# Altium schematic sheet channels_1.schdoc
size 400 x 299 mm; Device: default420x319; Symbol: default420x319; Name: default420x319; Size: "User"; Id: /; File: channels_1; Sheet: /
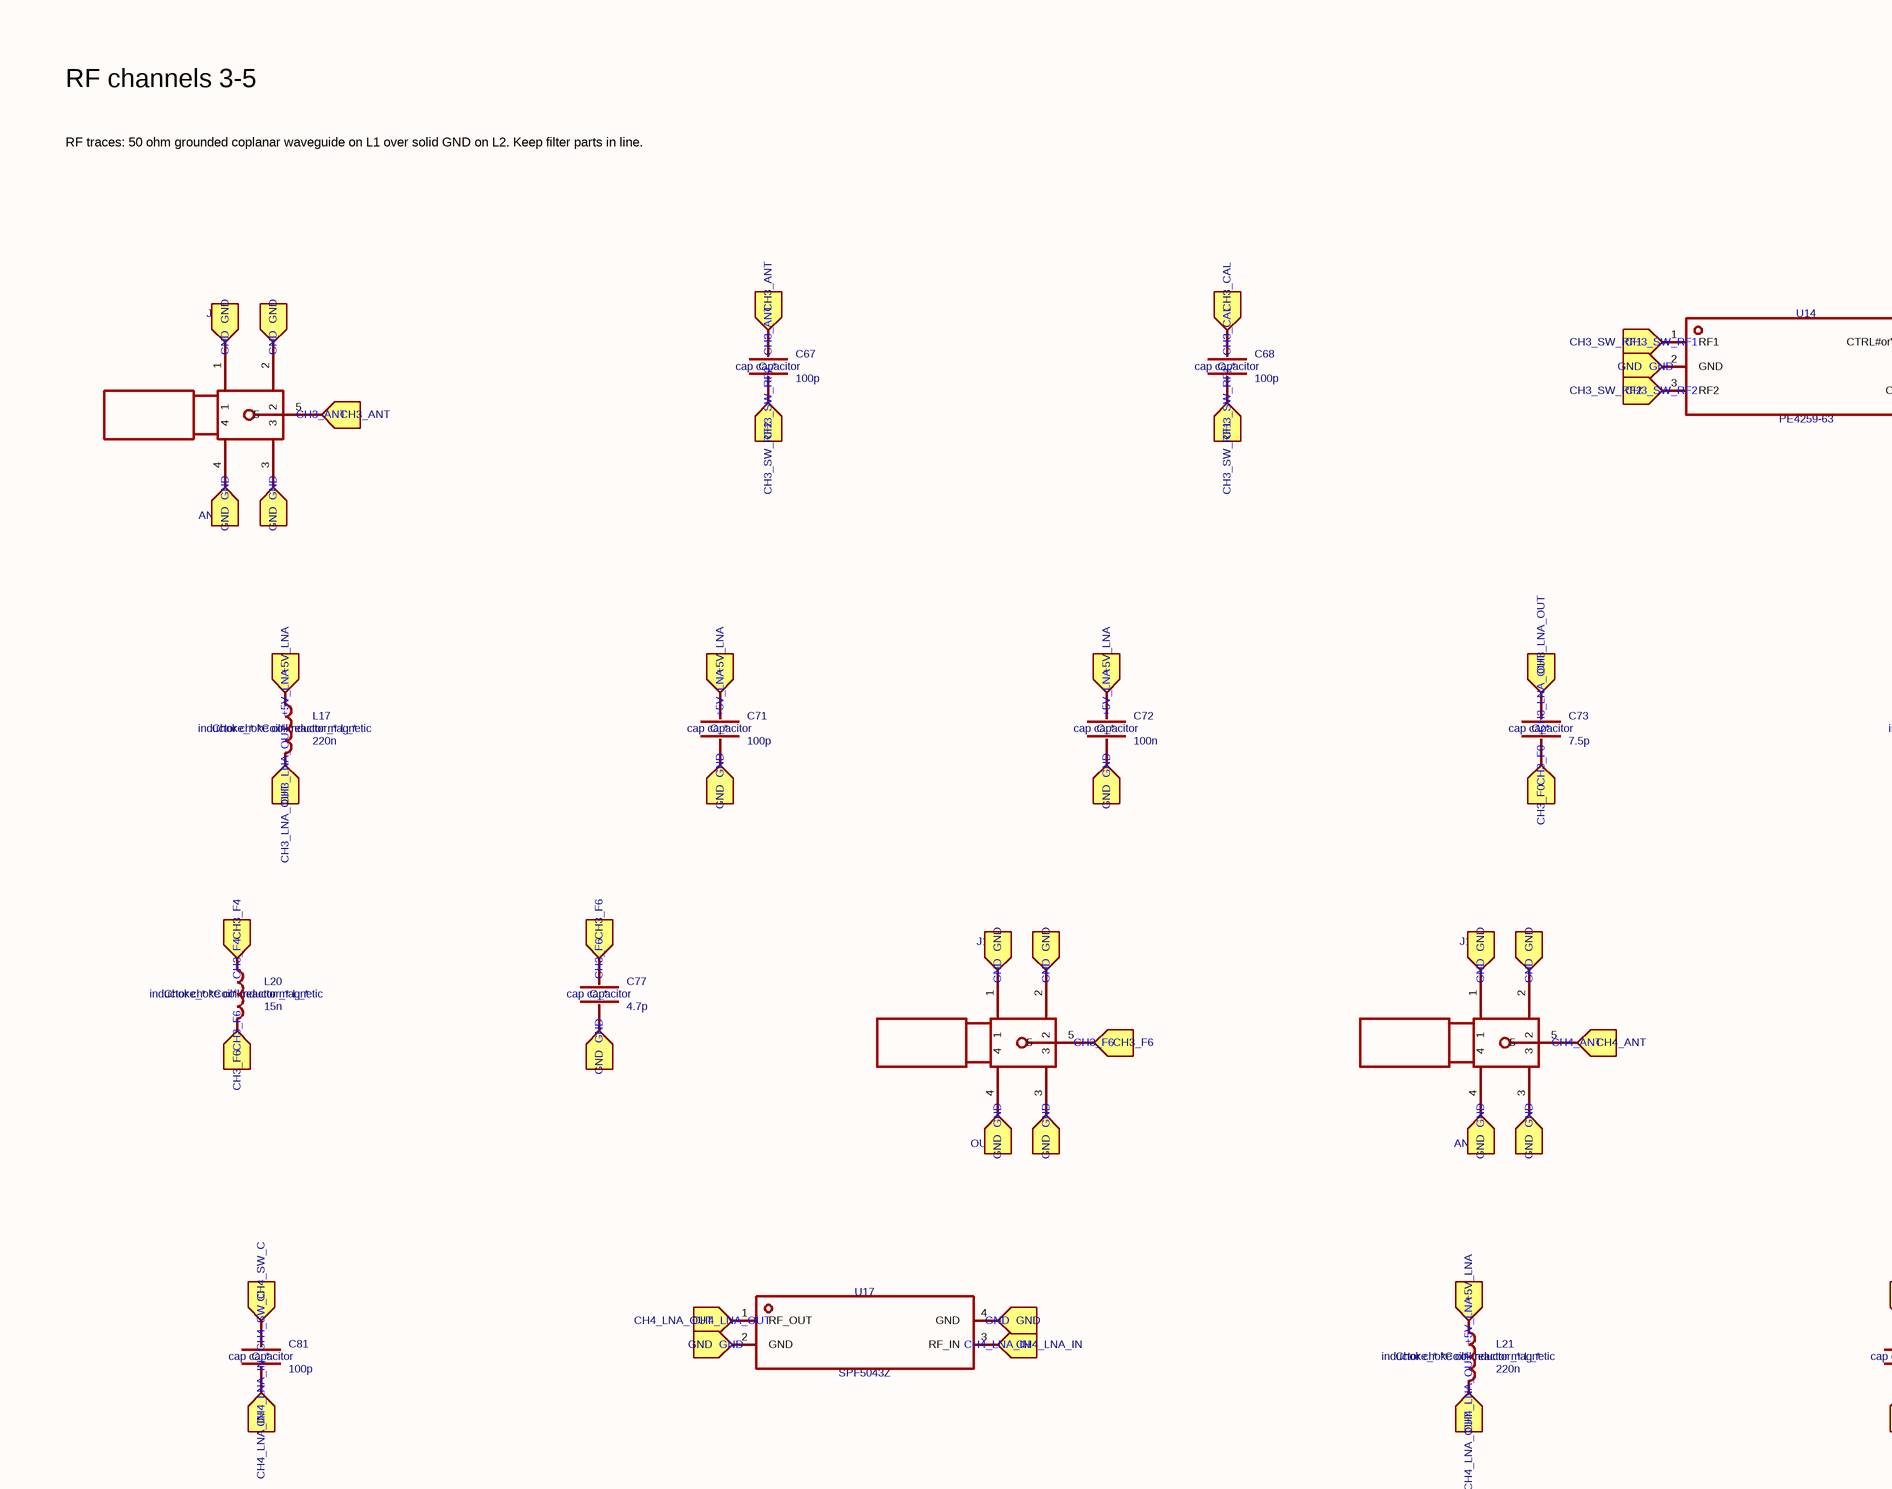
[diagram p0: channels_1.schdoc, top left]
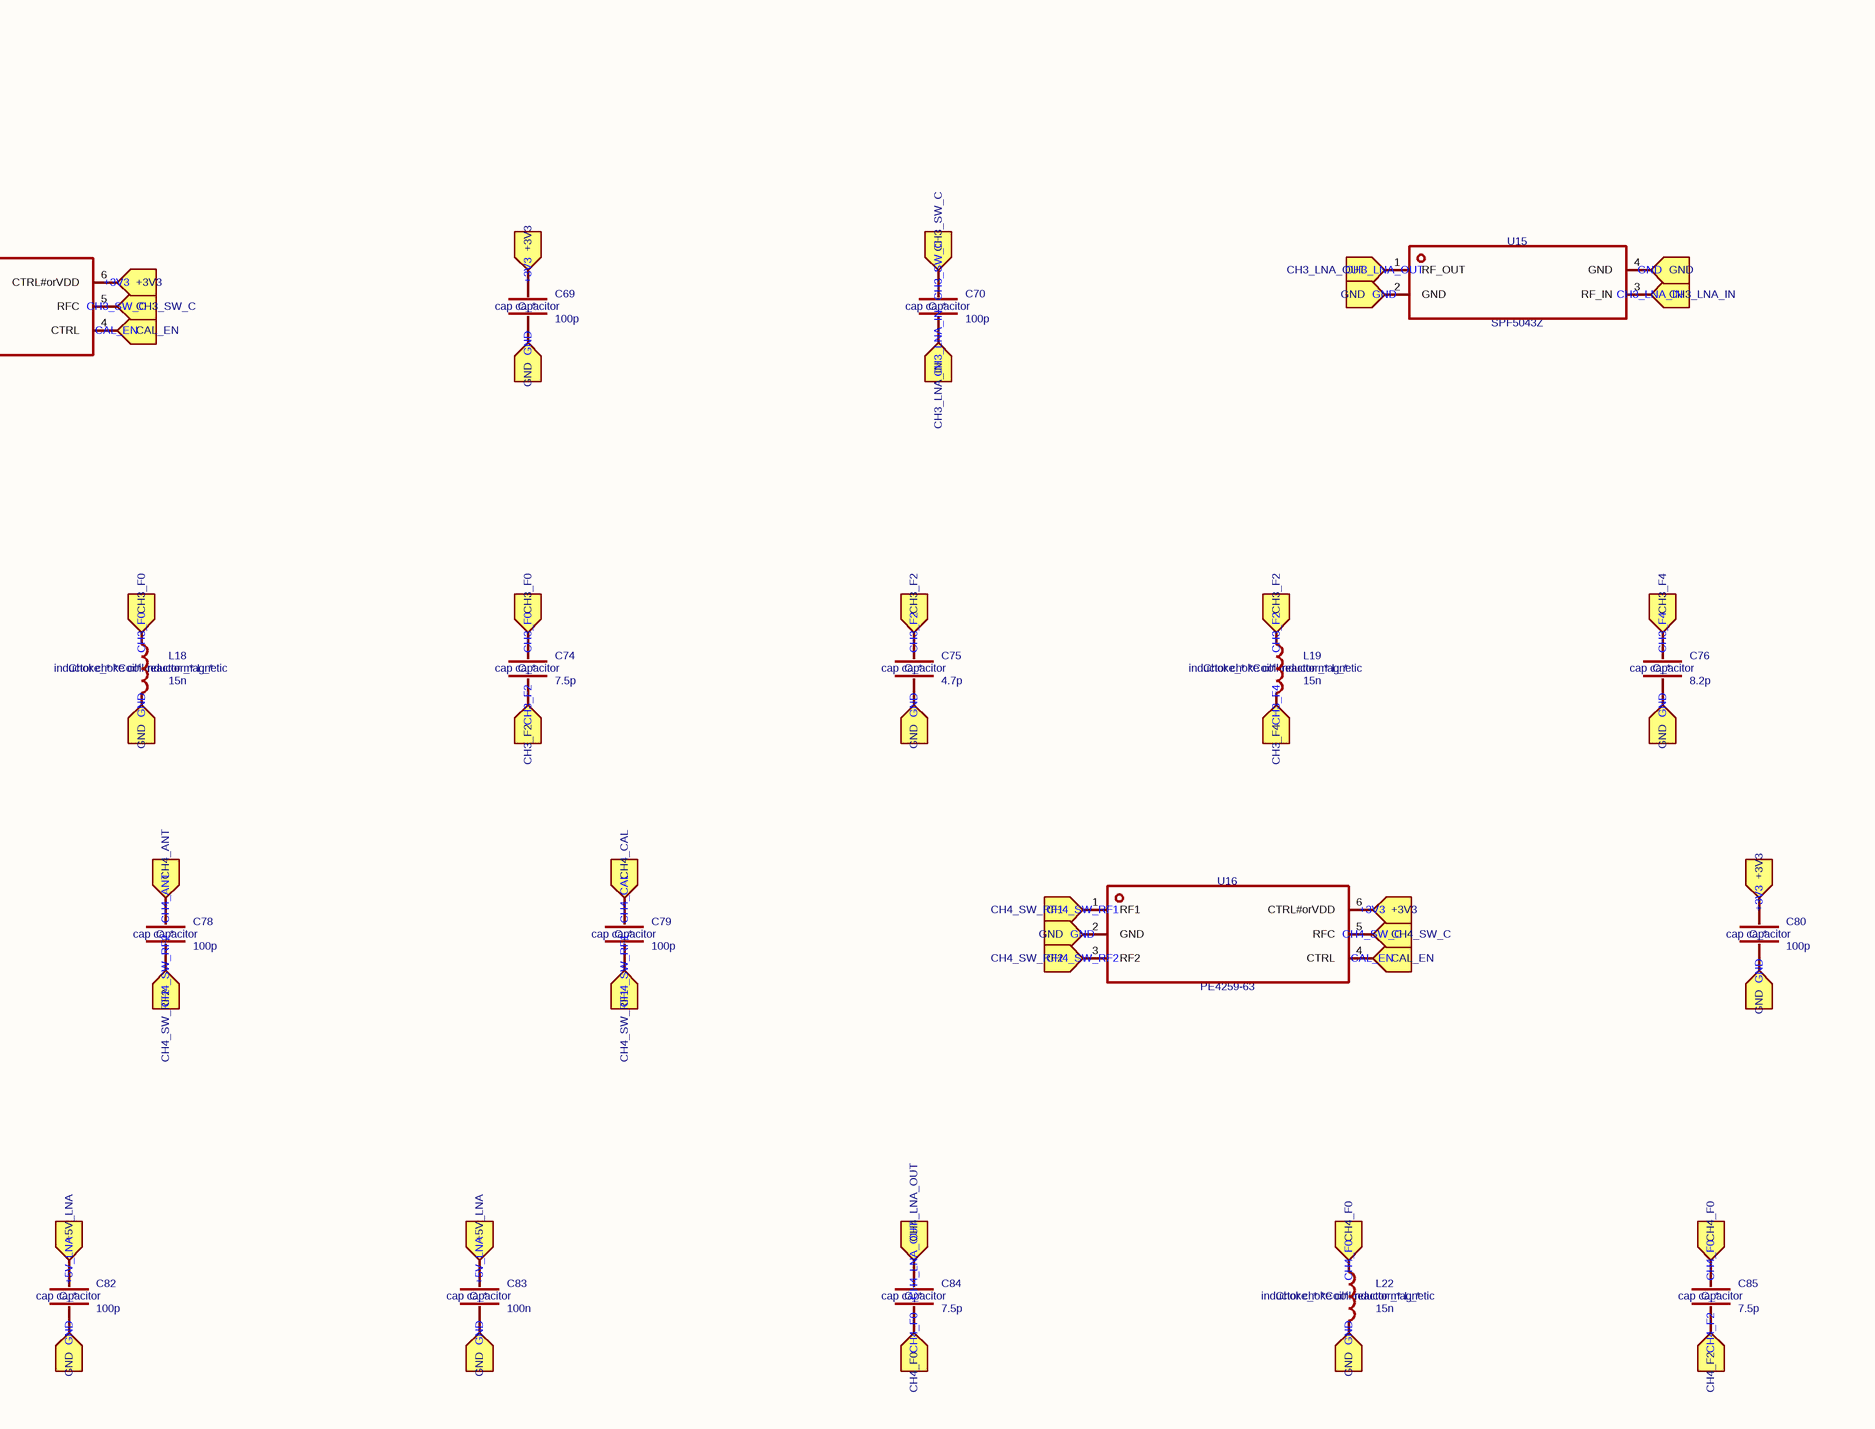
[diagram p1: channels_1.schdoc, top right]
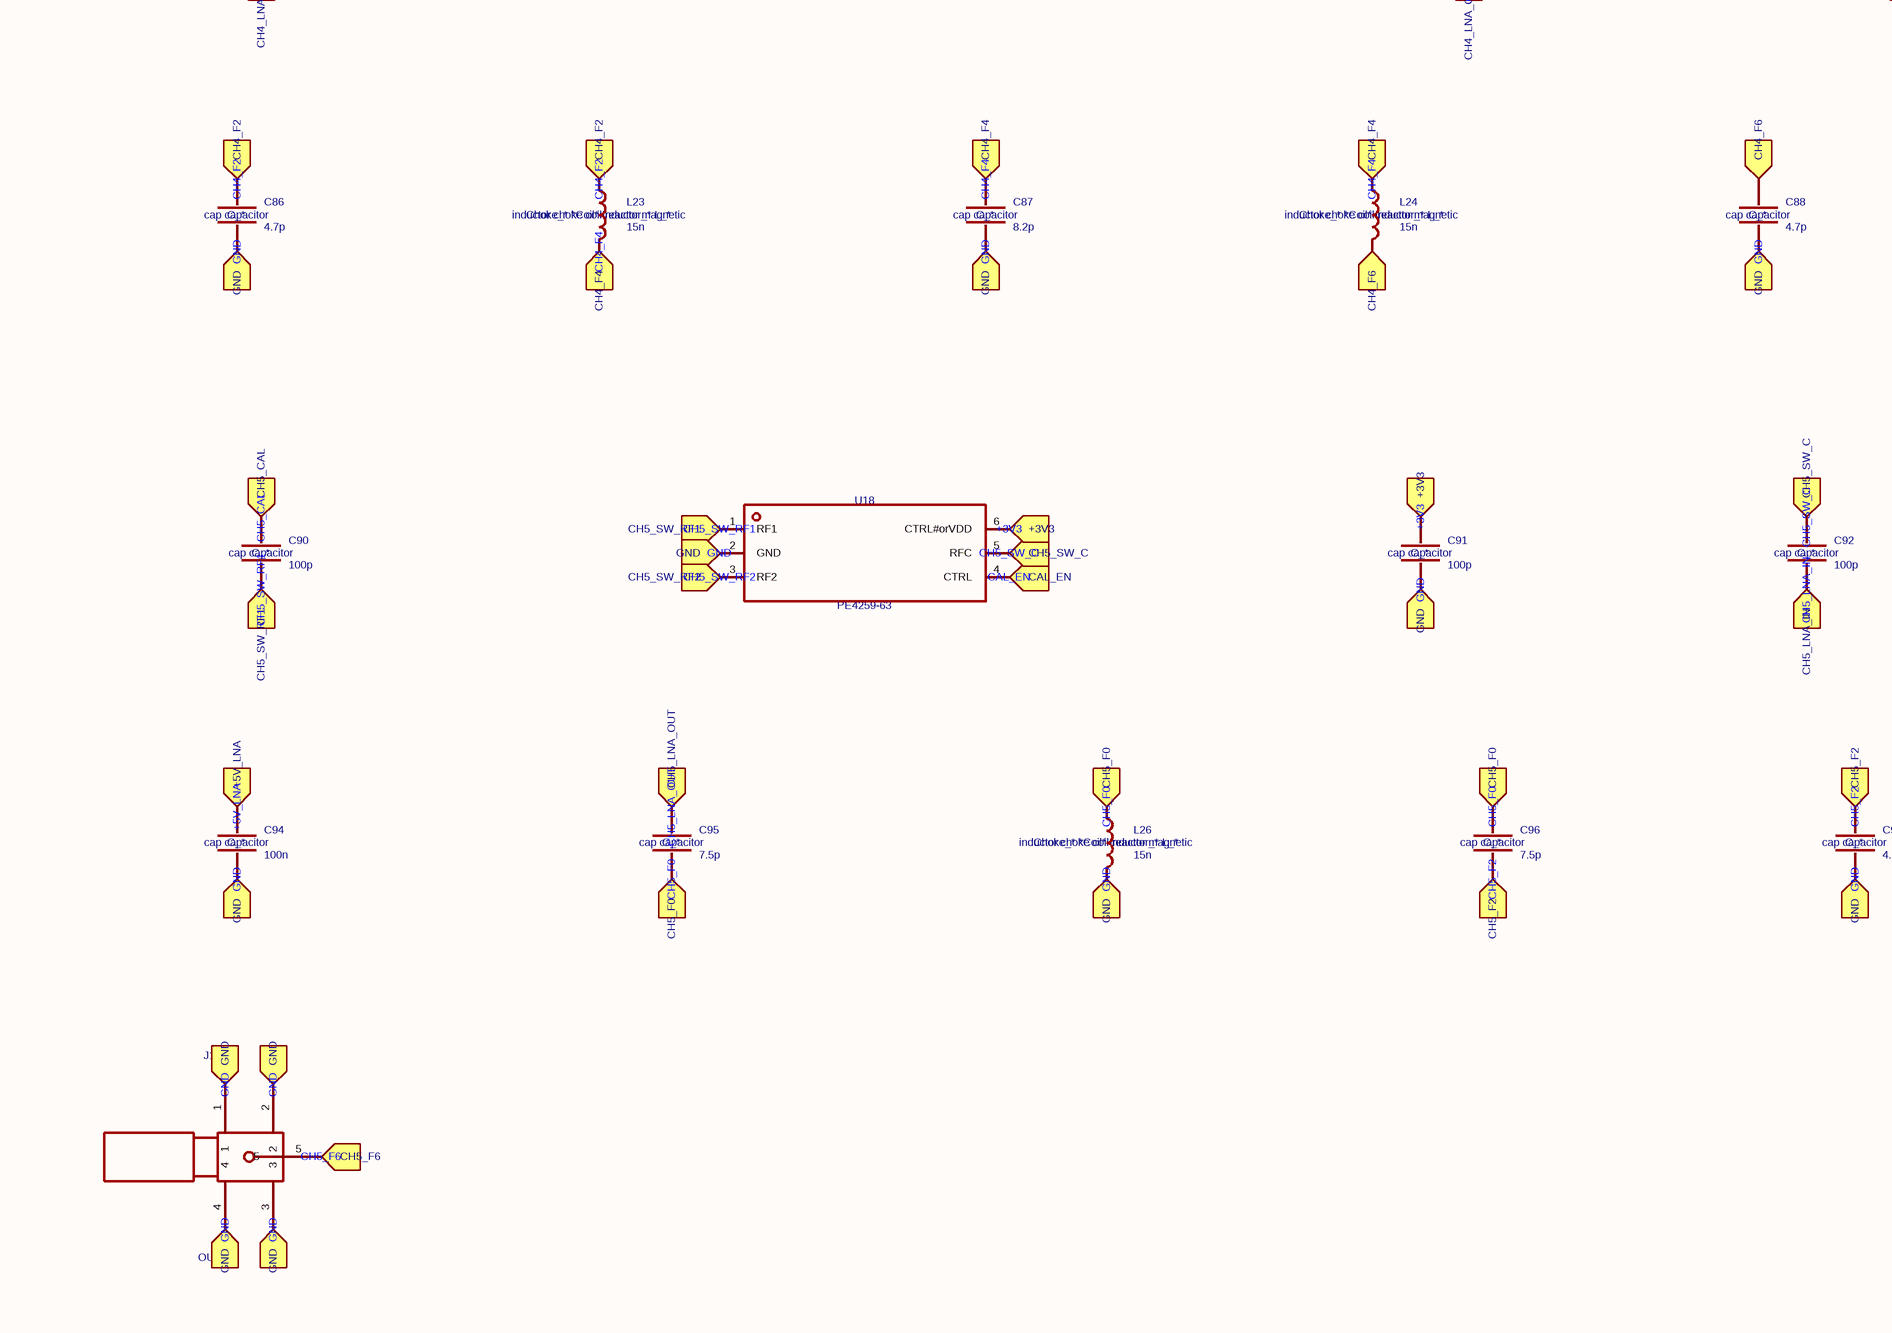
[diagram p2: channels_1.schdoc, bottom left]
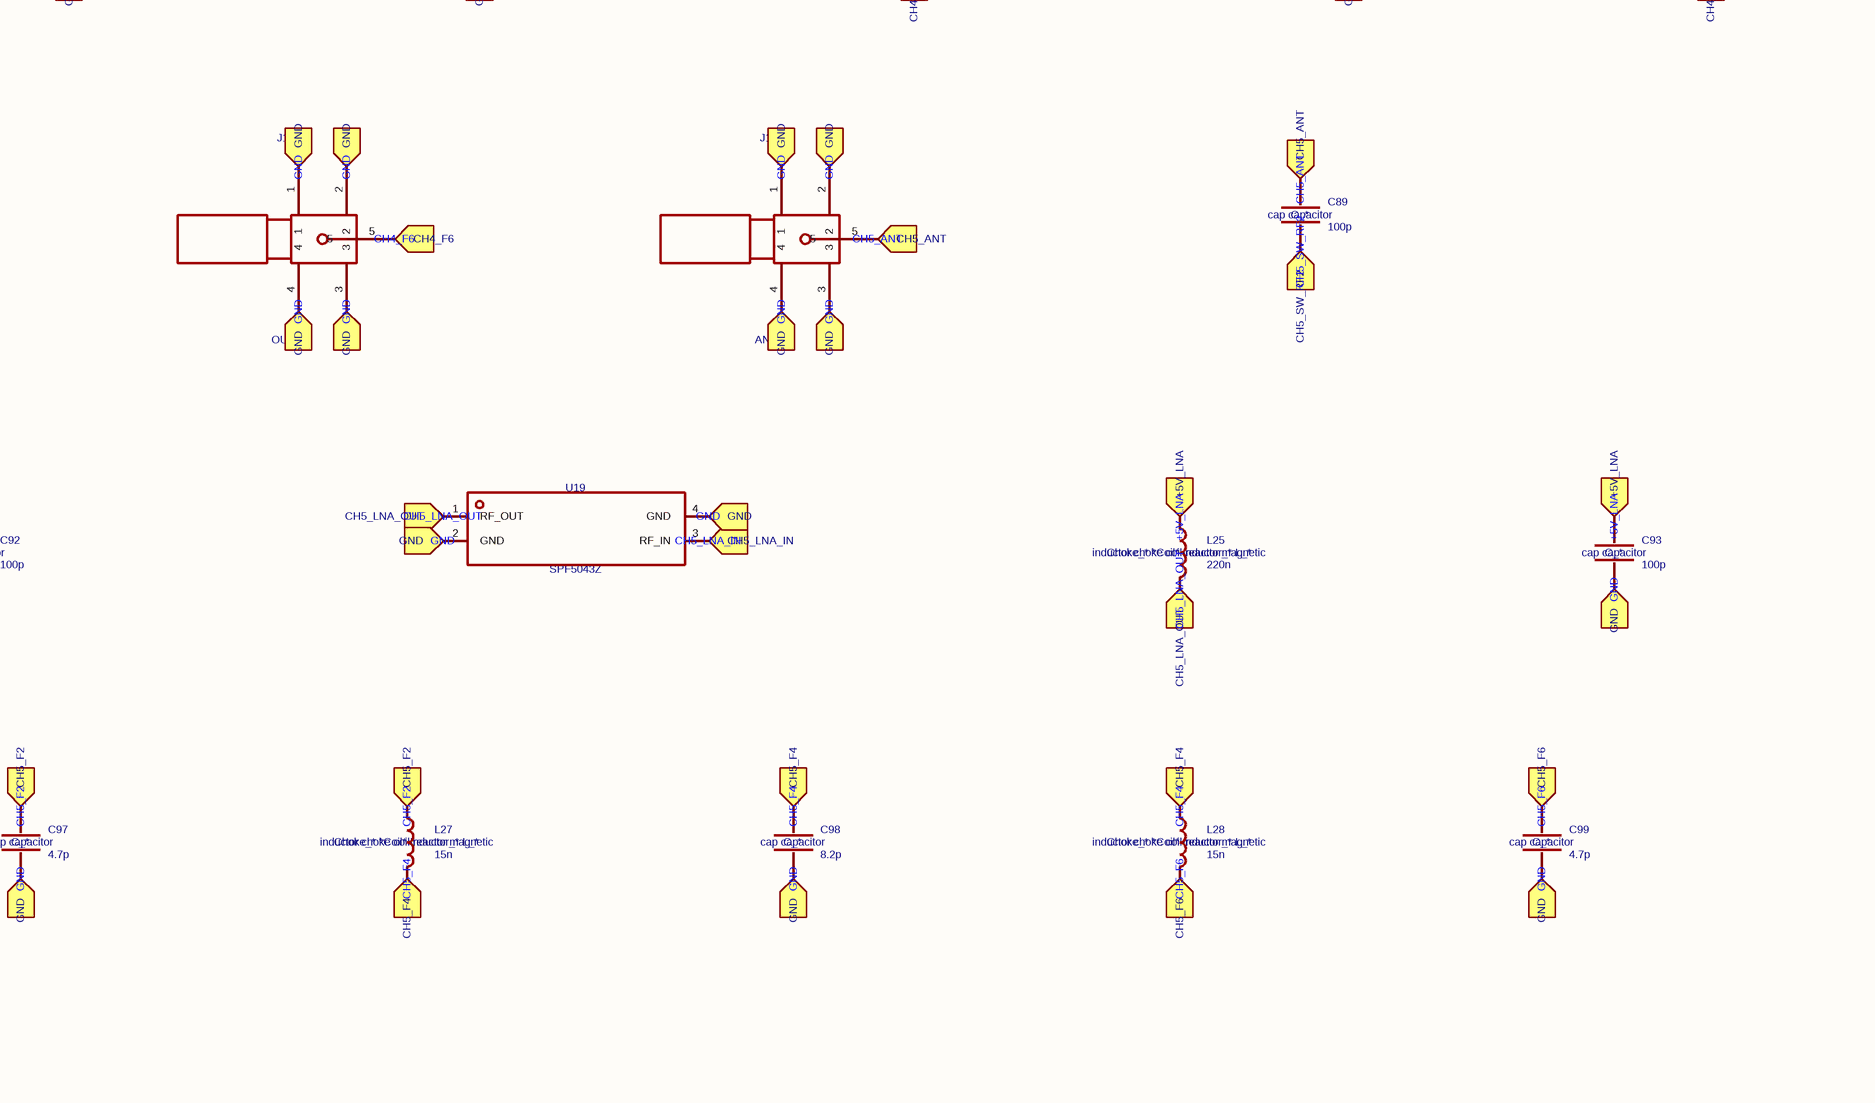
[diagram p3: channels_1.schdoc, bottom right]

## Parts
C67  value 100p  ki_keywords: cap capacitor  ki_fp_filters: C_*  [Capacitor_SMD:C_0402_1005Metric]  (hidden comment: Device_C)
C68  value 100p  ki_keywords: cap capacitor  ki_fp_filters: C_*  [Capacitor_SMD:C_0402_1005Metric]  (hidden comment: Device_C)
C69  value 100p  ki_keywords: cap capacitor  ki_fp_filters: C_*  [Capacitor_SMD:C_0402_1005Metric]  (hidden comment: Device_C)
C70  value 100p  ki_keywords: cap capacitor  ki_fp_filters: C_*  [Capacitor_SMD:C_0402_1005Metric]  (hidden comment: Device_C)
C71  value 100p  ki_keywords: cap capacitor  ki_fp_filters: C_*  [Capacitor_SMD:C_0402_1005Metric]  (hidden comment: Device_C)
C72  value 100n  ki_keywords: cap capacitor  ki_fp_filters: C_*  [Capacitor_SMD:C_0402_1005Metric]  (hidden comment: Device_C)
C73  value 7.5p  ki_keywords: cap capacitor  ki_fp_filters: C_*  [Capacitor_SMD:C_0402_1005Metric]  (hidden comment: Device_C)
C74  value 7.5p  ki_keywords: cap capacitor  ki_fp_filters: C_*  [Capacitor_SMD:C_0402_1005Metric]  (hidden comment: Device_C)
C75  value 4.7p  ki_keywords: cap capacitor  ki_fp_filters: C_*  [Capacitor_SMD:C_0402_1005Metric]  (hidden comment: Device_C)
C76  value 8.2p  ki_keywords: cap capacitor  ki_fp_filters: C_*  [Capacitor_SMD:C_0402_1005Metric]  (hidden comment: Device_C)
C77  value 4.7p  ki_keywords: cap capacitor  ki_fp_filters: C_*  [Capacitor_SMD:C_0402_1005Metric]  (hidden comment: Device_C)
C78  value 100p  ki_keywords: cap capacitor  ki_fp_filters: C_*  [Capacitor_SMD:C_0402_1005Metric]  (hidden comment: Device_C)
C79  value 100p  ki_keywords: cap capacitor  ki_fp_filters: C_*  [Capacitor_SMD:C_0402_1005Metric]  (hidden comment: Device_C)
C80  value 100p  ki_keywords: cap capacitor  ki_fp_filters: C_*  [Capacitor_SMD:C_0402_1005Metric]  (hidden comment: Device_C)
C81  value 100p  ki_keywords: cap capacitor  ki_fp_filters: C_*  [Capacitor_SMD:C_0402_1005Metric]  (hidden comment: Device_C)
C82  value 100p  ki_keywords: cap capacitor  ki_fp_filters: C_*  [Capacitor_SMD:C_0402_1005Metric]  (hidden comment: Device_C)
C83  value 100n  ki_keywords: cap capacitor  ki_fp_filters: C_*  [Capacitor_SMD:C_0402_1005Metric]  (hidden comment: Device_C)
C84  value 7.5p  ki_keywords: cap capacitor  ki_fp_filters: C_*  [Capacitor_SMD:C_0402_1005Metric]  (hidden comment: Device_C)
C85  value 7.5p  ki_keywords: cap capacitor  ki_fp_filters: C_*  [Capacitor_SMD:C_0402_1005Metric]  (hidden comment: Device_C)
C86  value 4.7p  ki_keywords: cap capacitor  ki_fp_filters: C_*  [Capacitor_SMD:C_0402_1005Metric]  (hidden comment: Device_C)
C87  value 8.2p  ki_keywords: cap capacitor  ki_fp_filters: C_*  [Capacitor_SMD:C_0402_1005Metric]  (hidden comment: Device_C)
C88  value 4.7p  ki_keywords: cap capacitor  ki_fp_filters: C_*  [Capacitor_SMD:C_0402_1005Metric]  (hidden comment: Device_C)
C89  value 100p  ki_keywords: cap capacitor  ki_fp_filters: C_*  [Capacitor_SMD:C_0402_1005Metric]  (hidden comment: Device_C)
C90  value 100p  ki_keywords: cap capacitor  ki_fp_filters: C_*  [Capacitor_SMD:C_0402_1005Metric]  (hidden comment: Device_C)
C91  value 100p  ki_keywords: cap capacitor  ki_fp_filters: C_*  [Capacitor_SMD:C_0402_1005Metric]  (hidden comment: Device_C)
C92  value 100p  ki_keywords: cap capacitor  ki_fp_filters: C_*  [Capacitor_SMD:C_0402_1005Metric]  (hidden comment: Device_C)
C93  value 100p  ki_keywords: cap capacitor  ki_fp_filters: C_*  [Capacitor_SMD:C_0402_1005Metric]  (hidden comment: Device_C)
C94  value 100n  ki_keywords: cap capacitor  ki_fp_filters: C_*  [Capacitor_SMD:C_0402_1005Metric]  (hidden comment: Device_C)
C95  value 7.5p  ki_keywords: cap capacitor  ki_fp_filters: C_*  [Capacitor_SMD:C_0402_1005Metric]  (hidden comment: Device_C)
C96  value 7.5p  ki_keywords: cap capacitor  ki_fp_filters: C_*  [Capacitor_SMD:C_0402_1005Metric]  (hidden comment: Device_C)
C97  value 4.7p  ki_keywords: cap capacitor  ki_fp_filters: C_*  [Capacitor_SMD:C_0402_1005Metric]  (hidden comment: Device_C)
C98  value 8.2p  ki_keywords: cap capacitor  ki_fp_filters: C_*  [Capacitor_SMD:C_0402_1005Metric]  (hidden comment: Device_C)
C99  value 4.7p  ki_keywords: cap capacitor  ki_fp_filters: C_*  [Capacitor_SMD:C_0402_1005Metric]  (hidden comment: Device_C)
J9  value ANT3  [prc:SMA-TH_BWSMA-KE-Z001]  (hidden comment: prc_BWSMA-KE-Z001)
J10  value OUT3  [prc:SMA-TH_BWSMA-KE-Z001]  (hidden comment: prc_BWSMA-KE-Z001)
J11  value ANT4  [prc:SMA-TH_BWSMA-KE-Z001]  (hidden comment: prc_BWSMA-KE-Z001)
J12  value OUT4  [prc:SMA-TH_BWSMA-KE-Z001]  (hidden comment: prc_BWSMA-KE-Z001)
J13  value ANT5  [prc:SMA-TH_BWSMA-KE-Z001]  (hidden comment: prc_BWSMA-KE-Z001)
J14  value OUT5  [prc:SMA-TH_BWSMA-KE-Z001]  (hidden comment: prc_BWSMA-KE-Z001)
L17  value 220n  ki_keywords: inductor choke coil reactor magnetic  ki_fp_filters: Choke_* *Coil* Inductor_* L_*  [Inductor_SMD:L_0603_1608Metric]  (hidden comment: Device_L)
L18  value 15n  ki_keywords: inductor choke coil reactor magnetic  ki_fp_filters: Choke_* *Coil* Inductor_* L_*  [Inductor_SMD:L_0402_1005Metric]  (hidden comment: Device_L)
L19  value 15n  ki_keywords: inductor choke coil reactor magnetic  ki_fp_filters: Choke_* *Coil* Inductor_* L_*  [Inductor_SMD:L_0402_1005Metric]  (hidden comment: Device_L)
L20  value 15n  ki_keywords: inductor choke coil reactor magnetic  ki_fp_filters: Choke_* *Coil* Inductor_* L_*  [Inductor_SMD:L_0402_1005Metric]  (hidden comment: Device_L)
L21  value 220n  ki_keywords: inductor choke coil reactor magnetic  ki_fp_filters: Choke_* *Coil* Inductor_* L_*  [Inductor_SMD:L_0603_1608Metric]  (hidden comment: Device_L)
L22  value 15n  ki_keywords: inductor choke coil reactor magnetic  ki_fp_filters: Choke_* *Coil* Inductor_* L_*  [Inductor_SMD:L_0402_1005Metric]  (hidden comment: Device_L)
L23  value 15n  ki_keywords: inductor choke coil reactor magnetic  ki_fp_filters: Choke_* *Coil* Inductor_* L_*  [Inductor_SMD:L_0402_1005Metric]  (hidden comment: Device_L)
L24  value 15n  ki_keywords: inductor choke coil reactor magnetic  ki_fp_filters: Choke_* *Coil* Inductor_* L_*  [Inductor_SMD:L_0402_1005Metric]  (hidden comment: Device_L)
L25  value 220n  ki_keywords: inductor choke coil reactor magnetic  ki_fp_filters: Choke_* *Coil* Inductor_* L_*  [Inductor_SMD:L_0603_1608Metric]  (hidden comment: Device_L)
L26  value 15n  ki_keywords: inductor choke coil reactor magnetic  ki_fp_filters: Choke_* *Coil* Inductor_* L_*  [Inductor_SMD:L_0402_1005Metric]  (hidden comment: Device_L)
L27  value 15n  ki_keywords: inductor choke coil reactor magnetic  ki_fp_filters: Choke_* *Coil* Inductor_* L_*  [Inductor_SMD:L_0402_1005Metric]  (hidden comment: Device_L)
L28  value 15n  ki_keywords: inductor choke coil reactor magnetic  ki_fp_filters: Choke_* *Coil* Inductor_* L_*  [Inductor_SMD:L_0402_1005Metric]  (hidden comment: Device_L)
U14  value PE4259-63  [prc:SC-70-6_L2.2-W1.3-P0.65-LS2.1-BL]  (hidden comment: prc_PE4259-63)
U15  value SPF5043Z  [prc:SOT343_L2.0-W1.3-P1.30-LS2.1-BL]  (hidden comment: prc_SPF5043Z)
U16  value PE4259-63  [prc:SC-70-6_L2.2-W1.3-P0.65-LS2.1-BL]  (hidden comment: prc_PE4259-63)
U17  value SPF5043Z  [prc:SOT343_L2.0-W1.3-P1.30-LS2.1-BL]  (hidden comment: prc_SPF5043Z)
U18  value PE4259-63  [prc:SC-70-6_L2.2-W1.3-P0.65-LS2.1-BL]  (hidden comment: prc_PE4259-63)
U19  value SPF5043Z  [prc:SOT343_L2.0-W1.3-P1.30-LS2.1-BL]  (hidden comment: prc_SPF5043Z)

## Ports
+3V3 (in), +5V_LNA (in), CAL_EN (in), CH3_ANT (in), CH3_CAL (in), CH3_F0 (in), CH3_F2 (in), CH3_F4 (in), CH3_F6 (in), CH3_LNA_IN (in), CH3_LNA_OUT (in), CH3_SW_C (in), CH3_SW_RF1 (in), CH3_SW_RF2 (in), CH4_ANT (in), CH4_CAL (in), CH4_F0 (in), CH4_F2 (in), CH4_F4 (in), CH4_F6 (in), CH4_LNA_IN (in), CH4_LNA_OUT (in), CH4_SW_C (in), CH4_SW_RF1 (in), CH4_SW_RF2 (in), CH5_ANT (in), CH5_CAL (in), CH5_F0 (in), CH5_F2 (in), CH5_F4 (in), CH5_F6 (in), CH5_LNA_IN (in), CH5_LNA_OUT (in), CH5_SW_C (in), CH5_SW_RF1 (in), CH5_SW_RF2 (in), GND (in)

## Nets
+3V3: C69.1 C80.1 C91.1 U14.6(CTRL#orVDD) U16.6(CTRL#orVDD) U18.6(CTRL#orVDD) ; port +3V3
+5V_LNA: C71.1 C72.1 C82.1 C83.1 C93.1 C94.1 L17.1 L21.1 L25.1 ; port +5V_LNA
CAL_EN: U14.4(CTRL) U16.4(CTRL) U18.4(CTRL) ; port CAL_EN
CH3_ANT: C67.1 J9.5 ; port CH3_ANT
CH3_CAL: C68.1 ; port CH3_CAL
CH3_F0: C73.2 C74.1 L18.1 ; port CH3_F0
CH3_F2: C74.2 C75.1 L19.1 ; port CH3_F2
CH3_F4: C76.1 L19.2 L20.1 ; port CH3_F4
CH3_F6: C77.1 J10.5 L20.2 ; port CH3_F6
CH3_LNA_IN: C70.2 U15.3(RF_IN) ; port CH3_LNA_IN
CH3_LNA_OUT: C73.1 L17.2 U15.1(RF_OUT) ; port CH3_LNA_OUT
CH3_SW_C: C70.1 U14.5(RFC) ; port CH3_SW_C
CH3_SW_RF1: C68.2 U14.1(RF1) ; port CH3_SW_RF1
CH3_SW_RF2: C67.2 U14.3(RF2) ; port CH3_SW_RF2
CH4_ANT: C78.1 J11.5 ; port CH4_ANT
CH4_CAL: C79.1 ; port CH4_CAL
CH4_F0: C84.2 C85.1 L22.1 ; port CH4_F0
CH4_F2: C85.2 C86.1 L23.1 ; port CH4_F2
CH4_F4: C87.1 L23.2 L24.1 ; port CH4_F4
CH4_F6: C88.1 J12.5 L24.2 ; port CH4_F6
CH4_LNA_IN: C81.2 U17.3(RF_IN) ; port CH4_LNA_IN
CH4_LNA_OUT: C84.1 L21.2 U17.1(RF_OUT) ; port CH4_LNA_OUT
CH4_SW_C: C81.1 U16.5(RFC) ; port CH4_SW_C
CH4_SW_RF1: C79.2 U16.1(RF1) ; port CH4_SW_RF1
CH4_SW_RF2: C78.2 U16.3(RF2) ; port CH4_SW_RF2
CH5_ANT: C89.1 J13.5 ; port CH5_ANT
CH5_CAL: C90.1 ; port CH5_CAL
CH5_F0: C95.2 C96.1 L26.1 ; port CH5_F0
CH5_F2: C96.2 C97.1 L27.1 ; port CH5_F2
CH5_F4: C98.1 L27.2 L28.1 ; port CH5_F4
CH5_F6: C99.1 J14.5 L28.2 ; port CH5_F6
CH5_LNA_IN: C92.2 U19.3(RF_IN) ; port CH5_LNA_IN
CH5_LNA_OUT: C95.1 L25.2 U19.1(RF_OUT) ; port CH5_LNA_OUT
CH5_SW_C: C92.1 U18.5(RFC) ; port CH5_SW_C
CH5_SW_RF1: C90.2 U18.1(RF1) ; port CH5_SW_RF1
CH5_SW_RF2: C89.2 U18.3(RF2) ; port CH5_SW_RF2
GND: C69.2 C71.2 C72.2 C75.2 C76.2 C77.2 C80.2 C82.2 C83.2 C86.2 C87.2 C88.2 C91.2 C93.2 C94.2 C97.2 C98.2 C99.2 J9.1 J9.2 J9.3 J9.4 J10.1 J10.2 J10.3 J10.4 J11.1 J11.2 J11.3 J11.4 J12.1 J12.2 J12.3 J12.4 J13.1 J13.2 J13.3 J13.4 J14.1 J14.2 J14.3 J14.4 L18.2 L22.2 L26.2 U14.2(GND) U15.2(GND) U15.4(GND) U16.2(GND) U17.2(GND) U17.4(GND) U18.2(GND) U19.2(GND) U19.4(GND) ; port GND

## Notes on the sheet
- RF channels 3-5
- RF traces: 50 ohm grounded coplanar waveguide on L1 over solid GND on L2. Keep filter parts in line.

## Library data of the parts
C67 = Device_C: UniqueId: 790facc1dd52bc03; KiLib_Generator: SMD_2terminal_chip_molded; AddInBom: yes
C68 = Device_C: UniqueId: 695de859447a278b; KiLib_Generator: SMD_2terminal_chip_molded; AddInBom: yes
C69 = Device_C: UniqueId: ed5e3f159d100c7c; KiLib_Generator: SMD_2terminal_chip_molded; AddInBom: yes
C70 = Device_C: UniqueId: ef22f62b38d240f9; KiLib_Generator: SMD_2terminal_chip_molded; AddInBom: yes
C71 = Device_C: UniqueId: 13c458815c86755b; KiLib_Generator: SMD_2terminal_chip_molded; AddInBom: yes
C72 = Device_C: UniqueId: 4c445f6b18a98c19; KiLib_Generator: SMD_2terminal_chip_molded; AddInBom: yes
C73 = Device_C: UniqueId: ed67743022cf1596; KiLib_Generator: SMD_2terminal_chip_molded; AddInBom: yes
C74 = Device_C: UniqueId: 428606a84a8f4e02; KiLib_Generator: SMD_2terminal_chip_molded; AddInBom: yes
C75 = Device_C: UniqueId: 94802851accbed84; KiLib_Generator: SMD_2terminal_chip_molded; AddInBom: yes
C76 = Device_C: UniqueId: e46c4319d3798579; KiLib_Generator: SMD_2terminal_chip_molded; AddInBom: yes
C77 = Device_C: UniqueId: d85eccf1df583bf1; KiLib_Generator: SMD_2terminal_chip_molded; AddInBom: yes
C78 = Device_C: UniqueId: 289a7498a46a83c5; KiLib_Generator: SMD_2terminal_chip_molded; AddInBom: yes
C79 = Device_C: UniqueId: 1d1687b72a359977; KiLib_Generator: SMD_2terminal_chip_molded; AddInBom: yes
C80 = Device_C: UniqueId: 2dbd9816442fdb9a; KiLib_Generator: SMD_2terminal_chip_molded; AddInBom: yes
C81 = Device_C: UniqueId: bdf2686215596067; KiLib_Generator: SMD_2terminal_chip_molded; AddInBom: yes
C82 = Device_C: UniqueId: 2ac4a713bdb27458; KiLib_Generator: SMD_2terminal_chip_molded; AddInBom: yes
C83 = Device_C: UniqueId: 2b2365c2d0e3ae99; KiLib_Generator: SMD_2terminal_chip_molded; AddInBom: yes
C84 = Device_C: UniqueId: ac7cf9eb5671d2c3; KiLib_Generator: SMD_2terminal_chip_molded; AddInBom: yes
C85 = Device_C: UniqueId: 6158349470ed1956; KiLib_Generator: SMD_2terminal_chip_molded; AddInBom: yes
C86 = Device_C: UniqueId: 043006a40a259ae3; KiLib_Generator: SMD_2terminal_chip_molded; AddInBom: yes
C87 = Device_C: UniqueId: ed052c5890e059ff; KiLib_Generator: SMD_2terminal_chip_molded; AddInBom: yes
C88 = Device_C: UniqueId: 909660952e1a96fd; KiLib_Generator: SMD_2terminal_chip_molded; AddInBom: yes
C89 = Device_C: UniqueId: f9bfd7a6531d354d; KiLib_Generator: SMD_2terminal_chip_molded; AddInBom: yes
C90 = Device_C: UniqueId: 5471cb5e6ead650e; KiLib_Generator: SMD_2terminal_chip_molded; AddInBom: yes
C91 = Device_C: UniqueId: de488198406d19e5; KiLib_Generator: SMD_2terminal_chip_molded; AddInBom: yes
C92 = Device_C: UniqueId: 7abe426619a81940; KiLib_Generator: SMD_2terminal_chip_molded; AddInBom: yes
C93 = Device_C: UniqueId: ecf0d2211b923647; KiLib_Generator: SMD_2terminal_chip_molded; AddInBom: yes
C94 = Device_C: UniqueId: 7c9a59bbe2a187d0; KiLib_Generator: SMD_2terminal_chip_molded; AddInBom: yes
C95 = Device_C: UniqueId: 57cde6634fc67369; KiLib_Generator: SMD_2terminal_chip_molded; AddInBom: yes
C96 = Device_C: UniqueId: 31c7e7eccc20d384; KiLib_Generator: SMD_2terminal_chip_molded; AddInBom: yes
C97 = Device_C: UniqueId: d8febf21116de1ec; KiLib_Generator: SMD_2terminal_chip_molded; AddInBom: yes
C98 = Device_C: UniqueId: d804bee1c3c181f9; KiLib_Generator: SMD_2terminal_chip_molded; AddInBom: yes
C99 = Device_C: UniqueId: adaa631d027ba959; KiLib_Generator: SMD_2terminal_chip_molded; AddInBom: yes
J9 = prc_BWSMA-KE-Z001: Manufacturer: BAT WIRELESS(蝙蝠无线); ki_keywords: RF Connectors / Coaxial Connectors; UniqueId: 14b2f8436ec73be4; AddInBom: yes
J10 = prc_BWSMA-KE-Z001: Manufacturer: BAT WIRELESS(蝙蝠无线); ki_keywords: RF Connectors / Coaxial Connectors; UniqueId: 19810ed2731c20b4; AddInBom: yes
J11 = prc_BWSMA-KE-Z001: Manufacturer: BAT WIRELESS(蝙蝠无线); ki_keywords: RF Connectors / Coaxial Connectors; UniqueId: d9503b6182e86bda; AddInBom: yes
J12 = prc_BWSMA-KE-Z001: Manufacturer: BAT WIRELESS(蝙蝠无线); ki_keywords: RF Connectors / Coaxial Connectors; UniqueId: 81192a87cd4e0892; AddInBom: yes
J13 = prc_BWSMA-KE-Z001: Manufacturer: BAT WIRELESS(蝙蝠无线); ki_keywords: RF Connectors / Coaxial Connectors; UniqueId: 4fb97ddf9141d37a; AddInBom: yes
J14 = prc_BWSMA-KE-Z001: Manufacturer: BAT WIRELESS(蝙蝠无线); ki_keywords: RF Connectors / Coaxial Connectors; UniqueId: d368ede5840df1df; AddInBom: yes
L17 = Device_L: UniqueId: 4e2cc9cdfaace8bd; KiLib_Generator: SMD_2terminal_chip_molded; AddInBom: yes
L18 = Device_L: UniqueId: ef274dca6664bd94; KiLib_Generator: SMD_2terminal_chip_molded; AddInBom: yes
L19 = Device_L: UniqueId: c2f96dd3d1060b29; KiLib_Generator: SMD_2terminal_chip_molded; AddInBom: yes
L20 = Device_L: UniqueId: 33d739b5b19e2cc1; KiLib_Generator: SMD_2terminal_chip_molded; AddInBom: yes
L21 = Device_L: UniqueId: d6084f5f3856b55f; KiLib_Generator: SMD_2terminal_chip_molded; AddInBom: yes
L22 = Device_L: UniqueId: fed822e2111ce1a4; KiLib_Generator: SMD_2terminal_chip_molded; AddInBom: yes
L23 = Device_L: UniqueId: 10a0d6a7e42e00c6; KiLib_Generator: SMD_2terminal_chip_molded; AddInBom: yes
L24 = Device_L: UniqueId: 097f1e3fae8960a0; KiLib_Generator: SMD_2terminal_chip_molded; AddInBom: yes
L25 = Device_L: UniqueId: 2c0db95e7e518774; KiLib_Generator: SMD_2terminal_chip_molded; AddInBom: yes
L26 = Device_L: UniqueId: 7baa404b977f34c0; KiLib_Generator: SMD_2terminal_chip_molded; AddInBom: yes
L27 = Device_L: UniqueId: 9e1fb412f925f5d1; KiLib_Generator: SMD_2terminal_chip_molded; AddInBom: yes
L28 = Device_L: UniqueId: 8d3b36ae7104e519; KiLib_Generator: SMD_2terminal_chip_molded; AddInBom: yes
U14 = prc_PE4259-63: Manufacturer: pSemi(游隼半导体); ki_keywords: RF Switches; UniqueId: 8791d75d94e1481b; AddInBom: yes
U15 = prc_SPF5043Z: Manufacturer: Qorvo; ki_keywords: RF Amplifiers; UniqueId: 28995c53ef78d865; AddInBom: yes
U16 = prc_PE4259-63: Manufacturer: pSemi(游隼半导体); ki_keywords: RF Switches; UniqueId: ca4d2b64b6ec8380; AddInBom: yes
U17 = prc_SPF5043Z: Manufacturer: Qorvo; ki_keywords: RF Amplifiers; UniqueId: 1a5dee1823ef113a; AddInBom: yes
U18 = prc_PE4259-63: Manufacturer: pSemi(游隼半导体); ki_keywords: RF Switches; UniqueId: 3b01714176430545; AddInBom: yes
U19 = prc_SPF5043Z: Manufacturer: Qorvo; ki_keywords: RF Amplifiers; UniqueId: a4a6b0395ae03088; AddInBom: yes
